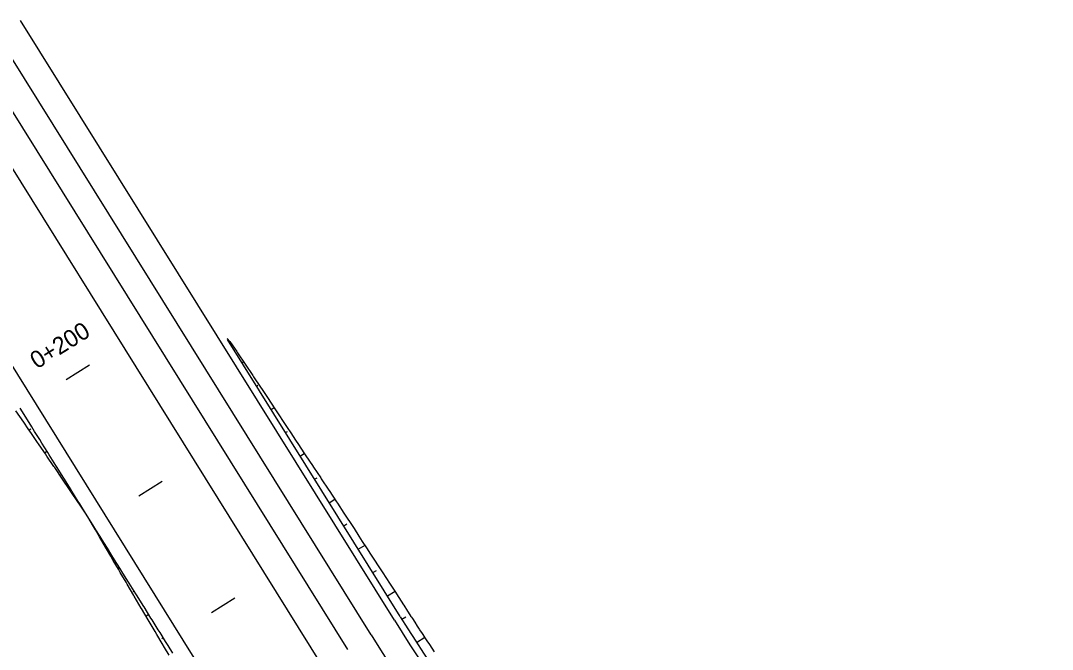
# Model space of a CAD drawing. Extents: x 6503541 to 6503743, y 5888004 to 5888145.
# Drawn here: x 6503696.036 to 6503697.838, y 5888110.578 to 5888111.676 of the extents above; entities that cross this region are included whole.
import ezdxf

# ---------------------------------------------------------------- set-up
doc = ezdxf.new("R2010")
doc.units = 0
doc.layers.add('12', color=7, linetype='Continuous')

msp = doc.modelspace()

# ---------------------------------------------------------------- linework, layer by layer
at = {"layer": '12'}
for p, q in [((6503696.689, 5888110.6284), (6503696.0362, 5888111.6758)), ((6503696.6483, 5888110.603), (6503695.9955, 5888111.6504)), ((6503696.6076, 5888110.5776), (6503695.9547, 5888111.625)), ((6503696.5628, 5888110.5496), (6503695.9143, 5888111.5901)), ((6503696.408, 5888110.4532), (6503695.7994, 5888111.4295)), ((6503696.6992, 5888110.6347), (6503696.3974, 5888111.119))]:
    msp.add_line(p, q, dxfattribs=at)
for points in [[(6503696.3971, 5888111.1204), (6503696.4017, 5888111.1156), (6503696.4137, 5888111.0976), (6503696.415, 5888111.0956), (6503696.4284, 5888111.0757), (6503696.4284, 5888111.0756), (6503696.4417, 5888111.0557), (6503696.4431, 5888111.0535), (6503696.455, 5888111.0357), (6503696.4578, 5888111.0315), (6503696.4683, 5888111.0157), (6503696.4724, 5888111.0094), (6503696.4815, 5888110.9957), (6503696.487, 5888110.9873), (6503696.4947, 5888110.9756), (6503696.5016, 5888110.9652), (6503696.508, 5888110.9556), (6503696.5163, 5888110.9431), (6503696.5213, 5888110.9356), (6503696.531, 5888110.9211), (6503696.5346, 5888110.9156), (6503696.5457, 5888110.899), (6503696.5479, 5888110.8956), (6503696.5603, 5888110.8769), (6503696.5611, 5888110.8756), (6503696.5744, 5888110.8556), (6503696.5749, 5888110.8548), (6503696.5876, 5888110.8355), (6503696.5894, 5888110.8327), (6503696.6007, 5888110.8154), (6503696.604, 5888110.8105), (6503696.6139, 5888110.7954), (6503696.6185, 5888110.7884), (6503696.627, 5888110.7753), (6503696.633, 5888110.7662), (6503696.6402, 5888110.7552), (6503696.6474, 5888110.744), (6503696.6533, 5888110.7351), (6503696.6619, 5888110.7218), (6503696.6663, 5888110.7149), (6503696.6763, 5888110.6996), (6503696.6794, 5888110.6948), (6503696.6907, 5888110.6773), (6503696.6924, 5888110.6746), (6503696.7051, 5888110.6551), (6503696.7054, 5888110.6545), (6503696.712, 5888110.6442), (6503696.7162, 5888110.6377), (6503696.718, 5888110.635), (6503696.7189, 5888110.6337), (6503696.7204, 5888110.6313), (6503696.7246, 5888110.6248), (6503696.7288, 5888110.6183), (6503696.7301, 5888110.6164), (6503696.7322, 5888110.6131), (6503696.7331, 5888110.6118), (6503696.7373, 5888110.6054), (6503696.7416, 5888110.5989), (6503696.7423, 5888110.5979), (6503696.7458, 5888110.5927), (6503696.7459, 5888110.5925), (6503696.7501, 5888110.5861), (6503696.7544, 5888110.5797), (6503696.7546, 5888110.5794), (6503696.7587, 5888110.5733)], [(6503696.3974, 5888111.119), (6503696.3983, 5888111.1196)], [(6503696.1158, 5888111.049), (6503696.1565, 5888111.0743)], [(6503696.4228, 5888111.0783), (6503696.426, 5888111.0803)], [(6503696.4482, 5888111.0375), (6503696.4504, 5888111.0389)], [(6503696.4735, 5888110.9968), (6503696.4791, 5888111.0003)], [(6503696.1535, 5888110.8091), (6503696.1493, 5888110.8153), (6503696.1388, 5888110.8311), (6503696.1359, 5888110.8353), (6503696.124, 5888110.8531), (6503696.1225, 5888110.8552), (6503696.1091, 5888110.875), (6503696.1091, 5888110.8751), (6503696.0957, 5888110.895), (6503696.0943, 5888110.897), (6503696.0822, 5888110.9149), (6503696.0794, 5888110.9189), (6503696.0687, 5888110.9348), (6503696.0645, 5888110.9409), (6503696.0552, 5888110.9546), (6503696.0496, 5888110.9628), (6503696.0417, 5888110.9745), (6503696.0281, 5888110.9943)], [(6503696.3019, 5888110.5711), (6503696.2937, 5888110.5843), (6503696.2892, 5888110.5915), (6503696.2797, 5888110.6068), (6503696.2766, 5888110.6118), (6503696.2657, 5888110.6293), (6503696.2639, 5888110.6322), (6503696.2517, 5888110.6518), (6503696.2512, 5888110.6526), (6503696.2385, 5888110.6729), (6503696.2376, 5888110.6743), (6503696.2258, 5888110.6933), (6503696.2236, 5888110.6967), (6503696.2131, 5888110.7137), (6503696.2096, 5888110.7192), (6503696.2004, 5888110.734), (6503696.1956, 5888110.7417), (6503696.1877, 5888110.7544), (6503696.1816, 5888110.7642), (6503696.175, 5888110.7748), (6503696.1676, 5888110.7866), (6503696.1623, 5888110.7951), (6503696.1536, 5888110.8091), (6503696.1496, 5888110.8155), (6503696.1396, 5888110.8316), (6503696.1369, 5888110.8359), (6503696.1256, 5888110.8541), (6503696.1242, 5888110.8562), (6503696.1116, 5888110.8765), (6503696.1115, 5888110.8766), (6503696.0988, 5888110.897), (6503696.0975, 5888110.899), (6503696.0861, 5888110.9173), (6503696.0835, 5888110.9215), (6503696.0734, 5888110.9377), (6503696.0695, 5888110.944), (6503696.0607, 5888110.9581), (6503696.0555, 5888110.9665), (6503696.048, 5888110.9784), (6503696.0354, 5888110.9988)], [(6503696.051, 5888110.9608), (6503696.0539, 5888110.9626)], [(6503696.4989, 5888110.9561), (6503696.5023, 5888110.9581)], [(6503696.078, 5888110.921), (6503696.0822, 5888110.9236)], [(6503696.5243, 5888110.9153), (6503696.5322, 5888110.9203)], [(6503696.1049, 5888110.8813), (6503696.1063, 5888110.8821)], [(6503696.5497, 5888110.8746), (6503696.5542, 5888110.8774)], [(6503696.1178, 5888110.8622), (6503696.1197, 5888110.8634)], [(6503696.2835, 5888110.8707), (6503696.2428, 5888110.8453)], [(6503696.5751, 5888110.8338), (6503696.5852, 5888110.8401)], [(6503696.2957, 5888110.5672), (6503696.2877, 5888110.5806), (6503696.2834, 5888110.5878), (6503696.2742, 5888110.6034), (6503696.2712, 5888110.6085), (6503696.2607, 5888110.6262), (6503696.2589, 5888110.6291), (6503696.2472, 5888110.649), (6503696.2467, 5888110.6498), (6503696.2346, 5888110.6705), (6503696.2338, 5888110.6718), (6503696.2224, 5888110.6912), (6503696.2204, 5888110.6947), (6503696.2103, 5888110.7119), (6503696.207, 5888110.7176), (6503696.1981, 5888110.7326), (6503696.1936, 5888110.7404), (6503696.186, 5888110.7534), (6503696.1803, 5888110.7633), (6503696.174, 5888110.7741), (6503696.1669, 5888110.7862), (6503696.1619, 5888110.7949), (6503696.1535, 5888110.8091)], [(6503696.1585, 5888110.8013), (6503696.1582, 5888110.8011)], [(6503696.6005, 5888110.7931), (6503696.606, 5888110.7966)], [(6503696.1838, 5888110.7606), (6503696.1831, 5888110.7601)], [(6503696.6259, 5888110.7524), (6503696.6378, 5888110.7598)], [(6503696.2092, 5888110.7198), (6503696.2066, 5888110.7182)], [(6503696.6513, 5888110.7116), (6503696.6576, 5888110.7156)], [(6503696.2346, 5888110.6791), (6503696.2328, 5888110.6779)], [(6503696.6767, 5888110.6709), (6503696.6901, 5888110.6793)], [(6503696.4104, 5888110.667), (6503696.3697, 5888110.6416)], [(6503696.26, 5888110.6384), (6503696.2553, 5888110.6354)], [(6503696.7021, 5888110.6302), (6503696.7091, 5888110.6346)], [(6503696.2854, 5888110.5976), (6503696.2826, 5888110.5958)], [(6503696.7278, 5888110.5897), (6503696.7422, 5888110.599)]]:
    msp.add_lwpolyline(points, dxfattribs=at)
for radius in [3.36, 3.348, 3.408]:
    msp.add_arc((6503699.5405, 5888112.4056), radius, 211.9347, 239.4389, dxfattribs=at)

# ---------------------------------------------------------------- texts
msp.add_text('0+200', height=0.03, rotation=31.9347, dxfattribs=at).set_placement((6503696.0647, 5888111.0664))

doc.saveas('drawing.dxf')
